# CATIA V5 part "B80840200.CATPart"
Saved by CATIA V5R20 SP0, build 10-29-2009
Part number: B80840200
Revision: 3
Definition: design
Nomenclature: B80840200
Source: made
Description: NOT SPECIFIED
Bounding box of the stored display mesh (mm): x -22.5 to 22.5, y -22.5 to 22.5, z 0 to 200
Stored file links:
  C:\Users\Raffaele\Desktop\3D X SITO CF\BOLEX\4-PILLAR REF 808\B80840200.CATPart
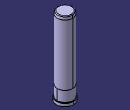
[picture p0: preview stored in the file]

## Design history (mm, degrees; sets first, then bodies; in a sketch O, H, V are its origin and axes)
Body1 "MANIFOLD_SOLID_BREP #450" (main body)
  Solid1: solid without history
